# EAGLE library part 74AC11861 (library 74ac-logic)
10-bit BUS BUFFER
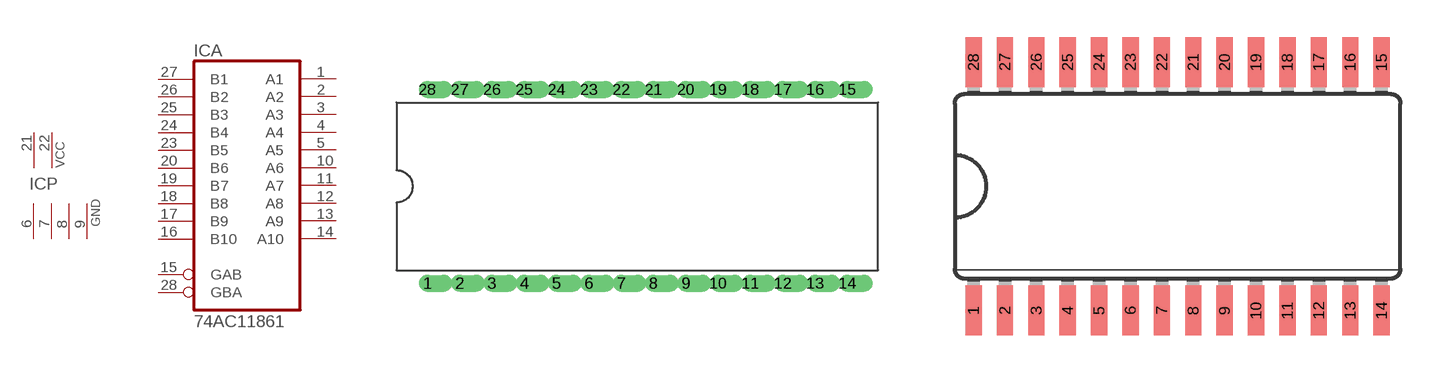
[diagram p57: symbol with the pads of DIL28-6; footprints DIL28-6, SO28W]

Designator prefix IC; gates A=7411861 P=2PWR4GND

## 74AC11861  [DIL28-6]
1  A:A1  hiz
2  A:A2  hiz
3  A:A3  hiz
4  A:A4  hiz
5  A:A5  hiz
6  P:GND  pwr
7  P:GND  pwr
8  P:GND  pwr
9  P:GND  pwr
10  A:A6  hiz
11  A:A7  hiz
12  A:A8  hiz
13  A:A9  hiz
14  A:A10  hiz
15  A:GAB  in
16  A:B10  in
17  A:B9  in
18  A:B8  in
19  A:B7  in
20  A:B6  in
21  P:VCC  pwr
22  P:VCC  pwr
23  A:B5  in
24  A:B4  in
25  A:B3  in
26  A:B2  in
27  A:B1  in
28  A:GBA  in

## 74AC11861D  [SO28W]
Pads as for DIL28-6

## Footprint DIL28-6 (pad centres in mm)
Dual In Line 0.6 inch
drill 0.813 offset: 1 -16.51,-7.62; 2 -13.97,-7.62; 3 -11.43,-7.62; 4 -8.89,-7.62; 5 -6.35,-7.62; 6 -3.81,-7.62; 7 -1.27,-7.62; 8 1.27,-7.62; 9 3.81,-7.62; 10 6.35,-7.62; 11 8.89,-7.62; 12 11.43,-7.62; 13 13.97,-7.62; 14 16.51,-7.62; 15 16.51,7.62; 16 13.97,7.62; 17 11.43,7.62; 18 8.89,7.62; 19 6.35,7.62; 20 3.81,7.62; 21 1.27,7.62; 22 -1.27,7.62; 23 -3.81,7.62; 24 -6.35,7.62; 25 -8.89,7.62; 26 -11.43,7.62; 27 -13.97,7.62; 28 -16.51,7.62

## Footprint SO28W (pad centres in mm)
Wide Small Outline package 300 mil
smd 0.66 x 2.032: 1 -8.255,-5.029; 2 -6.985,-5.029; 3 -5.715,-5.029; 4 -4.445,-5.029; 5 -3.175,-5.029; 6 -1.905,-5.029; 7 -0.635,-5.029; 8 0.635,-5.029; 9 1.905,-5.029; 10 3.175,-5.029; 11 4.445,-5.029; 12 5.715,-5.029; 13 6.985,-5.029; 14 8.255,-5.029; 15 8.255,5.029; 16 6.985,5.029; 17 5.715,5.029; 18 4.445,5.029; 19 3.175,5.029; 20 1.905,5.029; 21 0.635,5.029; 22 -0.635,5.029; 23 -1.905,5.029; 24 -3.175,5.029; 25 -4.445,5.029; 26 -5.715,5.029; 27 -6.985,5.029; 28 -8.255,5.029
